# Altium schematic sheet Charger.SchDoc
size A4; Organization: Altium Limited; Address1: L3, 12a Rodborough Rd; Address2: Frenchs Forest; Address3: NSW; Address4: Australia 2086
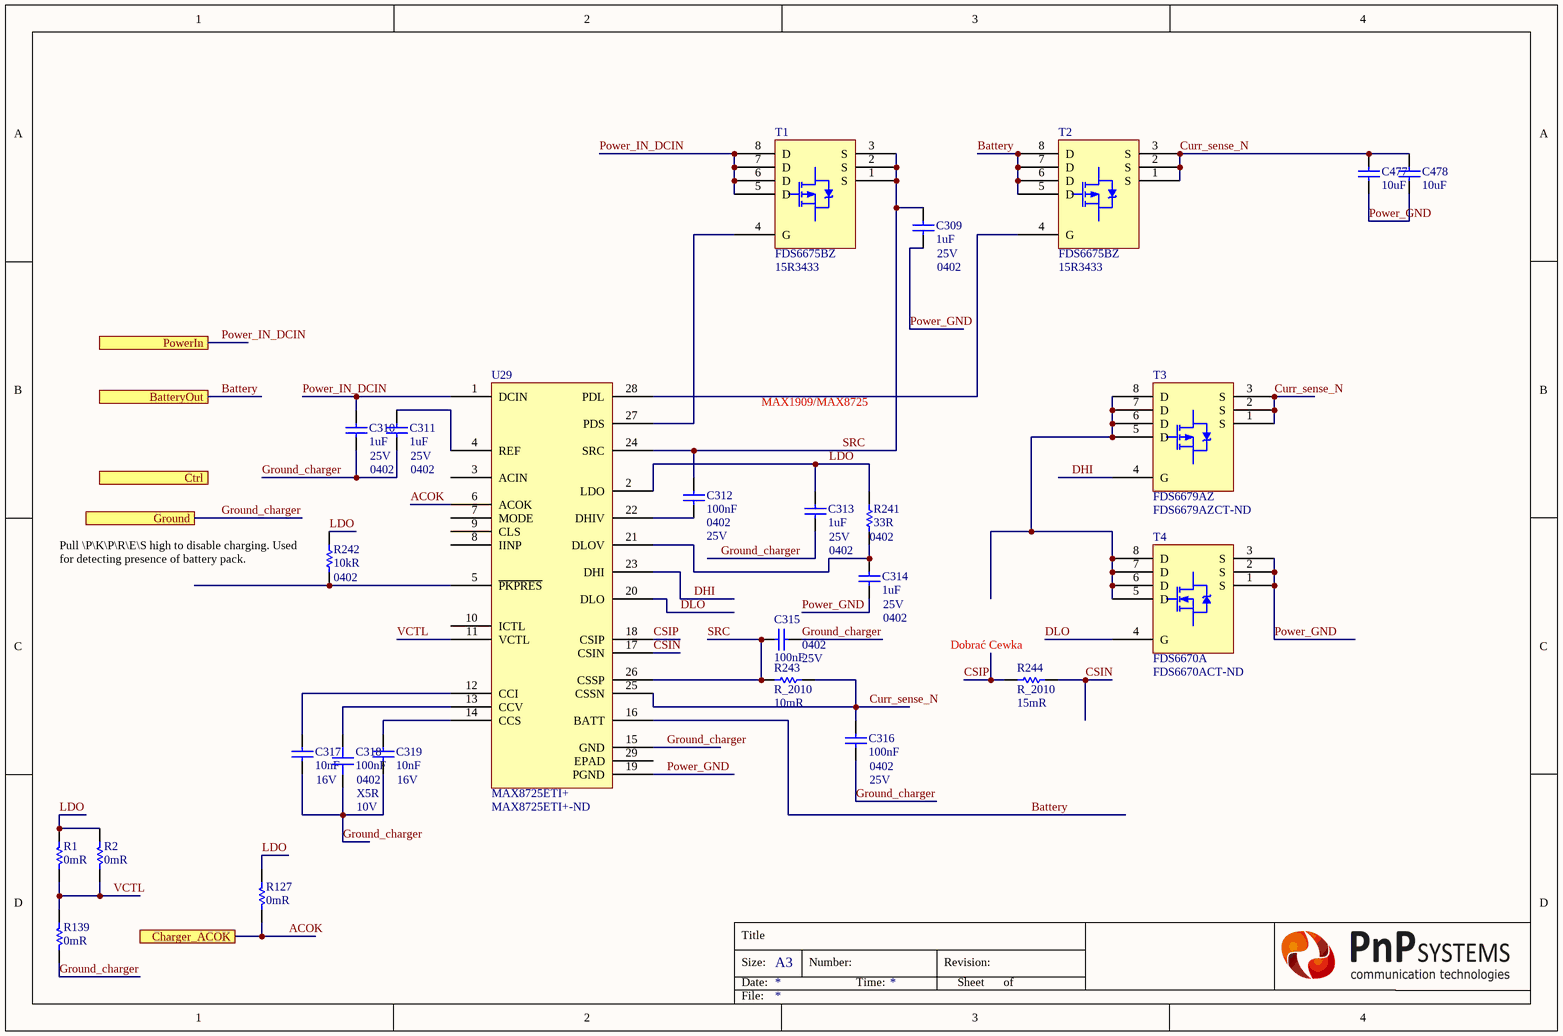
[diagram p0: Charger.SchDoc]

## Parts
C309  1uF  Case/Package: 0402  Voltage Rating: 25V  [CAP 0402/1005 RF]
C310  1uF  Case/Package: 0402  Voltage Rating: 25V  [CAP 0402/1005 RF]
C311  1uF  Case/Package: 0402  Voltage Rating: 25V  [CAP 0402/1005 RF]
C312  100nF  Case/Package: 0402  Voltage Rating: 25V  [CAP 0402/1005 RF]
C313  1uF  Case/Package: 0402  Voltage Rating: 25V  [CAP 0402/1005 RF]
C314  1uF  Case/Package: 0402  Voltage Rating: 25V  [CAP 0402/1005 RF]
C315  100nF  Case/Package: 0402  Voltage Rating: 25V  [CAP 0402/1005 RF]
C316  100nF  Case/Package: 0402  Voltage Rating: 25V  [CAP 0402/1005 RF]
C317  10nF  Voltage Rating (DC): 16V  [CAP 0201/0603 RF]
C318  100nF  Case/Package: 0402  Dielectric: X5R  Voltage Rating: 10V  [CAP 0402/1005 RF]
C319  10nF  Voltage Rating (DC): 16V  [CAP 0201/0603 RF]
C477  10uF  [CAP 1206/3216]
C478  10uF  [CAP 1206/3216]
R1  0mR  [RES 0402/1005 RF]
R2  0mR  [RES 0402/1005 RF]
R127  0mR  [RES 0402/1005 RF]
R139  0mR  [RES 0402/1005 RF]
R241  33R  Case/Package: 0402  [RES 0402/1005 RF]
R242  10kR  Case Code (Imperial): 0402  [RES 0402/1005 RF]
R243  R_2010  Parameter 1: 10mR  [RESC2010]
R244  R_2010  Parameter 1: 15mR  [RESC2010]
T1  FDS6675BZ  Supplier Part Number 1: 15R3433  [FDS6679AZ]
T2  FDS6675BZ  Supplier Part Number 1: 15R3433  [FDS6679AZ]
T3  FDS6679AZ  Supplier Part Number 1: FDS6679AZCT-ND  [FDS6679AZ]
T4  FDS6670A  Supplier Part Number 1: FDS6670ACT-ND  [FDS6679AZ]
U29  MAX8725ETI+  Supplier Part Number 1: MAX8725ETI+-ND  [MAX8725]

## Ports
BatteryOut, Charger_ACOK, Ctrl, Ground, PowerIn

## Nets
ACOK: R127.2 U29.6(ACOK) ; port Charger_ACOK
Battery: T2.5(D) T2.6(D) T2.7(D) T2.8(D) U29.16(BATT) ; port BatteryOut
CSIN: R244.1 U29.17(CSIN)
CSIP: R244.2 U29.18(CSIP)
Curr_sense_N: C316.2 C477.2 C478.2 R243.2 T2.1(S) T2.2(S) T2.3(S) T3.1(S) T3.2(S) T3.3(S) U29.25(CSSN)
DHI: T3.4(G) U29.23(DHI)
DLO: T4.4(G) U29.20(DLO)
Ground_charger: C310.1 C311.1 C313.1 C315.1 C316.1 C317.1 C318.1 C319.1 R139.2 U29.15(GND) ; port Ground
LDO: C313.2 R1.1 R2.1 R127.1 R241.2 R242.2 U29.2(LDO)
Power_GND: C309.1 C314.1 C477.1 C478.1 T4.1(S) T4.2(S) T4.3(S) U29.19(PGND)
Power_IN_DCIN: C310.2 T1.5(D) T1.6(D) T1.7(D) T1.8(D) U29.1(DCIN) ; port PowerIn
SRC: C309.2 C312.1 C315.2 R243.1 T1.1(S) T1.2(S) T1.3(S) U29.24(SRC) U29.26(CSSP)
VCTL: R1.2 R2.2 R139.1 U29.11(VCTL)
NetC311_2: C311.2 U29.4(REF)
NetC312_2: C312.2 U29.22(DHIV)
NetC314_2: C314.2 R241.1 U29.21(DLOV)
NetC317_2: C317.2 U29.12(CCI)
NetC318_2: C318.2 U29.13(CCV)
NetC319_2: C319.2 U29.14(CCS)
NetR242_1: R242.1 U29.5(~{PKPRES})
NetT1_4: T1.4(G) U29.27(PDS)
NetT2_4: T2.4(G) U29.28(PDL)
NetT3_5: T3.5(D) T3.6(D) T3.7(D) T3.8(D) T4.5(D) T4.6(D) T4.7(D) T4.8(D)

Not connected (* = marked no-connect by the designer): U29 3(ACIN) 7(MODE) 8(IINP) 9(CLS) 10(ICTL) 29(EPAD)

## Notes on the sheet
- MAX1909/MAX8725
- (near R242) Pull \P\K\P\R\E\S high to disable charging. Used for detecting presence of battery pack.
- (near R244) Dobrać Cewka

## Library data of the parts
C309-C311 C313 C314 = Capacitor: MURATA - GRT155R61E105KE01D - SMD Multilayer Ceramic Capacitor, 1 µF, 25 V, 0402 [1005 Metric], ± 10%, X5R, GRT Series - SMD Multilayer Ceramic Capacitor, 1 µF, 25 V, 0402 [1005 Metric], ± 10%, X5R, GRT Series
C312 C315 C316 = Capacitor: Cap Ceramic 0.1uF 25V X7R 20% SMD 0402 125C Paper T/R; Manufacturer: Murata; Manufacturer Part Number: GRM155R71E104ME14D
C317 C319 = Capacitor: CAP CER 10000PF 16V X7R 0201; Manufacturer: Murata; Manufacturer Part Number: GRM033R71C103KE14D; Tolerance: 10%
C318 = Capacitor: Manufacturer: Yageo; Manufacturer Part Number: CC0402KRX5R6BB104; Tolerance: 10%; Dissipation Factor: 5%; Insulation Resistance: 10GR
C477 C478 = Capacitor: Manufacturer 1: Murata; Manufacturer Part Number 1: GRM31CR71E106MA12L; Tolerance: 20%; Dielectric: X7R; Voltage Rating: 25V
R1 R2 R127 R139 = Resistor: Manufacturer 1: Yageo; Manufacturer Part Number 1: RC0402JR-070RL; Power Rating: 62.5mW; Tolerance: 5%; Voltage Rating: 50V; Max Power Dissipation: 63mW; Temperature Coefficient: 200ppm/°C
R241 = Resistor: Res Thick Film 0402 33 Ohm 1% 0.063W(1/16W) ±100ppm/C Epoxy Pad SMD T/R; Manufacturer: Yageo; Manufacturer Part Number: RC0402FR-0733RL; Power Rating: 62.5mW; Voltage Rating: 50V; Temperature Coefficient: 100ppm/°C
R242 = Resistor: RES 10K OHM 0.1% 1/16W 0402; Manufacturer: Stackpole Electronics; Manufacturer Part Number: RNCF0402BTE10K0; Max Power Dissipation: 63mW; Temperature Coefficient: 25ppm/°C
R243 = R_2010: RES 0.01 OHM 1% 1/2W 2010; Manufacturer: Vishay Dale; Manufacturer Part Number: WSL2010R0100FEA; Power Rating: 500mW; Voltage Rating: 70mV; Temperature Coefficient: 75ppm/°C
R244 = R_2010: RES SMD 15 MOHM 1% 1W 2010; Manufacturer: Vishay Dale; Manufacturer Part Number: WSL2010R0150FEA18; Temperature Coefficient: 75ppm/°C
T1 T2 = FDS6675BZ: ON SEMICONDUCTOR - FDS6675BZ - P CHANNEL MOSFET, -30V, -11A; Manufacturer: ON Semiconductor / Fairchild; Nominal Vgs: -2V; Rise Time: 7.8ns; Input Capacitance: 2.47nF; Max Power Dissipation: 2.5W; Number of Elements: 1; Rds On Max: 13mR; Continuous Drain Current (ID): 11A; Fall Time: 60ns; Drain to Source Resistance: 10.8mR; Turn-Off Delay Time: 120ns; Drain to Source Voltage (Vdss): 30V; Turn-On Delay Time: 3ns; Element Configuration: Single; Gate to Source Voltage (Vgs): 25V; On-State Resistance: 21.8MR
T3 = FDS6679AZ: MOSFET P-CH 30V 13A 8-SOIC; Manufacturer: ON Semiconductor / Fairchild; Max Power Dissipation: 2.5W; Number of Elements: 1; Rise Time: 15ns; Nominal Vgs: -1.9V; Rds On Max: 9.3mR; Input Capacitance: 3.845nF; Fall Time: 92ns; Turn-Off Delay Time: 210ns; Turn-On Delay Time: 13ns; Element Configuration: Single; Drain to Source Breakdown Voltage: -30V; Gate to Source Voltage (Vgs): 25V; Current Rating: -13A
T4 = FDS6670A: Trans MOSFET N-CH 30V 13A 8-Pin SOIC T/R; Manufacturer: ON Semiconductor / Fairchild; Rise Time: 13ns; Nominal Vgs: 1.8V; Rds On Max: 8mR; Input Capacitance: 2.22nF; Number of Elements: 1; Max Power Dissipation: 2.5W; Turn-Off Delay Time: 40ns; Turn-On Delay Time: 15ns; Element Configuration: Single; Gate to Source Voltage (Vgs): 20V
U29 = MAX8725ETI+: Battery Charger Lead-Acid/Li-Ion/Li-Pol/NiCD/NiMH 4000mA 17.65V 28-Pin TQFN EP; Manufacturer: Maxim Integrated; Output Current: 4A; Number of Cells: 4; Operating Supply Current: 2.7mA; Operating Supply Voltage: 28V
